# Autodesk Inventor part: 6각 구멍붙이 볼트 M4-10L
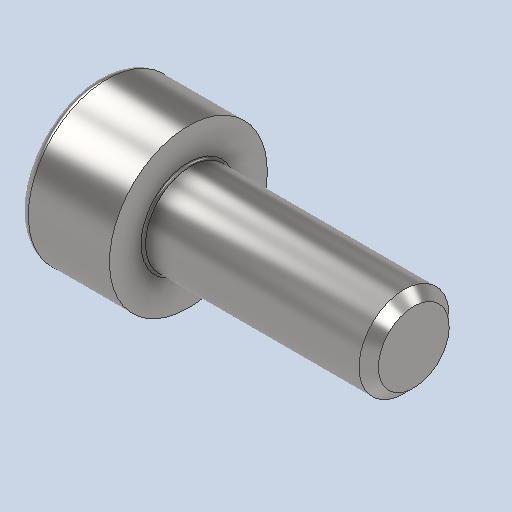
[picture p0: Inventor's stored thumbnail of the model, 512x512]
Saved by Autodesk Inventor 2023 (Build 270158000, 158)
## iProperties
Created: 2025-04
Part Number: 6각 구멍붙이 볼트 M4-10L
Material: 강철, 연강
Description: 6각머리 태핑 나사
Document SubType Name: Modeling
Designer: ADMIN_PC
Density: 7.86 g/cm^3
Appearance: 기본값
Author: jhkim
Revision Number: 1
Sending System: Autodesk Inventor 2026
Preprocessor: ST-DEVELOPER v20.1
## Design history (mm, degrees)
feature "Solid1"
node "솔리드1"
